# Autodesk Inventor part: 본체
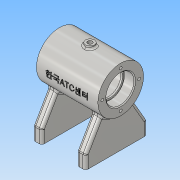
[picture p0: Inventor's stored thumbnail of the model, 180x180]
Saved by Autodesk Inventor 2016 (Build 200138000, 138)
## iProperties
Created: 2018-05
Part Number: 본체
Material: 알루미늄 6061
Document SubType Name: Modeling
Designer: Administrator
Density: 2.7 g/cm^3
Appearance: 알루미늄 - 평지
Mass: 317.681 g
Surface Area: 375.828 cm^2
Volume: 117.66 cm^3
Author: Administrator
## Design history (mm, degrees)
sketch "스케치1"
  geometry: L1 (-30, 35)-(30, 35); L2 (30, 35)-(30, -35); L3 (30, -35)-(-30, -35); L4 (-30, -35)-(-30, 35); L5 (-20, 35)-(-20, -35); L6 (20, 35)-(20, -35); 3 further points
  constraints: 12 end point, 4 point on line, 3 perpendicular, 2 midpoint, 2 parallel, 1 horizontal, 1 horizontal alignment, 1 vertical alignment
  dimensions: "d0" = 60 distance of L2.end L3.end; "d1" = 70 distance of L1.end L2.end; "d2" = 10 distance between parallel lines of L5 L4; "d3" = 10 distance between parallel lines of L2 L6
extrude "돌출1" new body sketch "스케치1" distance "d4" = 15; taper "d5" = 0 deg
sketch "스케치2"
  geometry: L1 (35, 65)-(-35, 65); L2 (35, 65)-(35, 91); L3 (35, 91)-(-35, 91); L4 (-35, 91)-(-35, 65); 2 further points
  constraints: 8 end point, 2 perpendicular, 1 horizontal, 1 midpoint, 1 vertical, 1 vertical alignment
  dimensions: "d7" = 65 distance from line of point (0, 0) L1; "d8" = 70 distance of L1.start L1.end; "d9" = 52 diameter of L3 L1
revolve "회전1" sketch "스케치2" stored, may be unused: angle "d10" = 90 deg
sketch "스케치3"
  geometry: L1 (0, 0)-(-15, 0) reference; L2 (-15, 0)-(-45.614, 17.675); L3 (0, 70)-(-15, 70) reference; L4 (-15, 70)-(-45.614, 52.325); L5 (-15, 0)-(-15, 70) reference; A1 r 26 centre (-65, 35) between (-45.614, 17.675) and (-45.614, 52.325) reference; 1 further point
  constraints: 4 end point, 2 point on circle
  dimensions: "d11" = 30 deg angle of L2 L1; "d12" = 30 deg angle of L4 L3
extrude "돌출2" join sketch "스케치3" distance "d13" = 10; taper "d14" = 0 deg
sketch "스케치4"
  geometry: L1 (0, 0)-(0, 119.378); L2 (0, 65)-(35.22, -31.765); L3 (9.919, 37.749)-(15.557, 39.801); L4 (15.557, 39.801)-(14.291, 43.28); L5 (14.291, 43.28)-(8.653, 41.227); L6 (8.653, 41.227)-(9.919, 37.749)
  constraints: 12 end point, 3 perpendicular, 2 point on line, 1 vertical, 2 other
  dimensions: "d15" = 20 deg angle of L2 L1; "d16" = 6 distance of L3.start L3.end; "d17" = 29 distance from line of L3 L2.start
revolve "회전2" sketch "스케치4" stored, may be unused: angle "d18" = 90 deg
sketch "스케치5"
  geometry: L1 (0, 94)-(5, 94); L2 (5, 94)-(5, 90.515); L3 (5, 90.515)-(0, 90.515); L4 (0, 90.515)-(0, 94); 3 further points
  constraints: 8 end point, 2 parallel, 1 horizontal, 1 midpoint, 1 perpendicular, 1 vertical alignment, 2 other
  dimensions: "d19" = 10 diameter of L2 L4; "d20" = 3 dimension on L1
revolve "회전3" sketch "스케치5" stored, may be unused: angle "d21" = 90 deg
sketch "스케치6"
  geometry: L1 (35, 65)-(-35, 65); L2 (-35, 65)-(-35, 81); L3 (-35, 81)-(-23, 81); L4 (-23, 81)-(-23, 79); L5 (-23, 79)-(-21, 79); L6 (-21, 79)-(-21, 86); L7 (-21, 86)-(21, 86); L8 (21, 86)-(21, 79); L9 (21, 79)-(23, 79); L10 (23, 79)-(23, 81); L11 (23, 81)-(35, 81); L12 (35, 81)-(35, 65); L13 (35, 39)-(35, 91) reference; 1 further point
  constraints: 24 end point, 9 perpendicular, 4 point on line, 2 collinear, 1 horizontal, 1 midpoint
  dimensions: "d22" = 65 distance from line of point (0, 0) L1; "d23" = 70 distance of L1.start L1.end; "d24" = 42 distance of L6.end L7.end; "d25" = 12 distance of L10.end L11.end; "d26" = 28 diameter of L9 L1; "d27" = 32 diameter of L11 L1; "d28" = 42 diameter of L7 L1
revolve "회전4" sketch "스케치6" stored, may be unused: angle "d29" = 90 deg
hole "구멍1" diameter "d32" = 5.188; stored, may be unused: countersink angle "d36" = 90 deg, drill point angle "d38" = 118 deg; dims "d30" = 10, "d31" = 10, "d33" = 12, "d34" = 4, "d35" = 2, "d37" = 16
hole "구멍2" diameter "d41" = 5.188; stored, may be unused: countersink angle "d45" = 90 deg, drill point angle "d47" = 118 deg; dims "d39" = 10, "d40" = 10, "d42" = 12, "d43" = 4, "d44" = 2, "d46" = 16
node "작업 평면1"
sketch "스케치7"
  geometry: L1 (-35, 26)-(-35, -26) reference; L2 (35, 26)-(-35, 26) reference; 2 further points
  constraints: 1 other
  dimensions: "d48" = 35 distance from line of point (0, 0) L1; "d49" = 26 distance from line of L2 point (0, 0)
feature "엠보싱1" sketch "스케치7" dims "d0" = 60, "d1" = 70, "d2" = 10, "d3" = 10, "d50" = 0.5, "d51" = 0
sketch "스케치8" dims "d52" = 42
  geometry: C1 r 16 at (0, 0) reference; 3 further points
  constraints: 2 horizontal alignment, 1 coincident, 2 other
hole "구멍3" sketch "스케치8" at (-21, 0) diameter "d53" = 3.242; stored, may be unused: countersink angle "d57" = 90 deg, drill point angle "d59" = 118 deg; dims "d54" = 8, "d55" = 4, "d56" = 2, "d58" = 10
hole "구멍4" diameter "d65" = 4.134; stored, may be unused: countersink angle "d69" = 90 deg, drill point angle "d71" = 118 deg; dims "d63" = 5, "d64" = 15, "d66" = 8, "d67" = 4, "d68" = 2, "d70" = 10
fillet "모깎기1" dims "d78" = 3
fillet "모깎기2" dims "d79" = 3
fillet "모깎기3" dims "d80" = 3
fillet "모깎기4" dims "d81" = 2
chamfer "모따기1" distance "d82" = 1; stored, may be unused: second distance "d83" = 2, angle "d84" = 45 deg
fillet "모깎기5" dims "d87" = 0.3
sketch "스케치10"
  geometry: L1 (-97.658, 0)-(50.448, 0); L2 (50.448, 0)-(50.448, -47.248); L3 (50.448, -47.248)-(-97.658, -47.248); L4 (-97.658, -47.248)-(-97.658, 0); 1 further point
  constraints: 8 end point, 2 parallel, 1 horizontal, 1 perpendicular
extrude "돌출3" cut sketch "스케치10" stored distance "d85" = 0; taper "d86" = 0 deg
node "솔리드1"
mirror "대칭1"
pattern_circular "원형 패턴1" dims angle "d61" = 360 deg
mirror "대칭2"
pattern_linear "직사각형 패턴1" dims "d74" = 50
